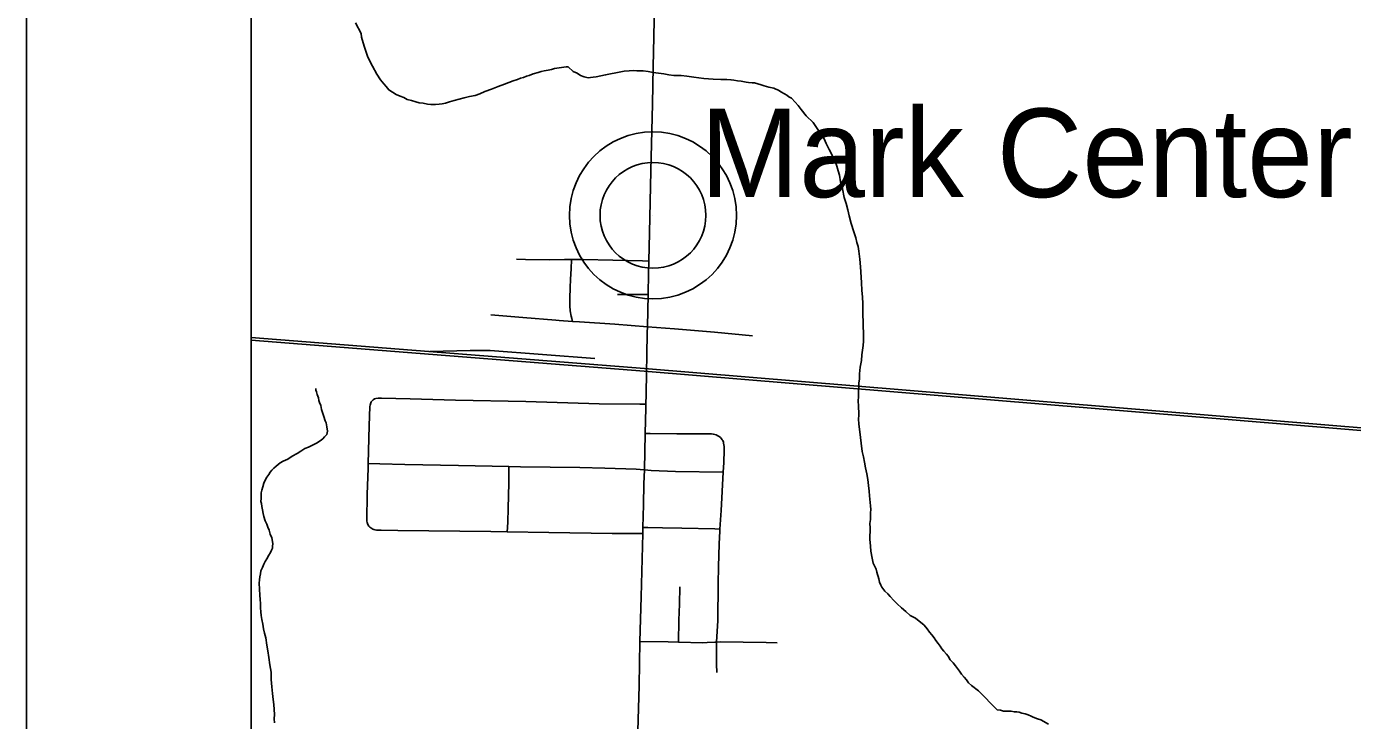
# Model space of a CAD drawing. Extents: x 2.1 to 73.9, y 4 to 26.
# Drawn here: x 41.859 to 42.449, y 23.011 to 23.321 of the extents above; entities that cross this region are included whole.
import ezdxf

# ---------------------------------------------------------------- set-up
doc = ezdxf.new("R2010")
doc.units = 0
for name, color, linetype in [('GM_X_County_Road', 7, 'Continuous'), ('GM_X_Minor_River', 7, 'Continuous'), ('GM_X_Rail_Line', 7, 'Continuous'), ('GM_X_Township_Road', 7, 'Continuous'), ('GM_X_Unincorporated', 7, 'Continuous'), ('GM_X_Unincorporated_Location', 7, 'Continuous'), ('GM_X_Unincorporated_Text', 7, 'Continuous'), ('SH_Data', 7, 'Continuous')]:
    doc.layers.add(name, color=color, linetype=linetype)

msp = doc.modelspace()

# ---------------------------------------------------------------- linework, layer by layer
at = {"layer": 'GM_X_County_Road'}
for p, q in [((42.13513, 23.18695), (42.13543, 23.20134)), ((42.13374, 23.12316), (42.13415, 23.13937)), ((42.13304, 23.09483), (42.1331, 23.09749))]:
    msp.add_line(p, q, dxfattribs=at)
for points in [[(42.13575, 23.21622), (42.13604, 23.22885), (42.13666, 23.25651), (42.13737, 23.28633), (42.13771, 23.30281), (42.13801, 23.31617), (42.13855, 23.34694), (42.13912, 23.37024), (42.13951, 23.39013), (42.1399, 23.40477)], [(42.13543, 23.20134), (42.13562, 23.21083), (42.13575, 23.21622)], [(42.13442, 23.15243), (42.13453, 23.15678), (42.13476, 23.16671), (42.13486, 23.17417), (42.13506, 23.18442), (42.13513, 23.18695)], [(42.13415, 23.13937), (42.13438, 23.15088), (42.13442, 23.15243)], [(42.1331, 23.09749), (42.13335, 23.10768), (42.13358, 23.11701), (42.13374, 23.12316)], [(42.13174, 23.04667), (42.13227, 23.06667), (42.13263, 23.07785), (42.13304, 23.09483)], [(42.12836, 22.90514), (42.1294, 22.94511), (42.13032, 22.98427), (42.13067, 23.00167), (42.13136, 23.02715), (42.13174, 23.04667)]]:
    msp.add_lwpolyline(points, dxfattribs=at)
at = {"layer": 'GM_X_Minor_River'}
for points in [[(42.00504, 23.32246), (42.00755, 23.31763), (42.00769, 23.31611), (42.0089, 23.31208), (42.01064, 23.30709), (42.0126, 23.30304), (42.01459, 23.29956), (42.01622, 23.29704), (42.01769, 23.29528), (42.01879, 23.29411), (42.01988, 23.29255), (42.02156, 23.29155), (42.02324, 23.29055), (42.02493, 23.28974), (42.02662, 23.28911), (42.02811, 23.28831), (42.03, 23.28787), (42.03188, 23.28724), (42.03339, 23.28681), (42.03529, 23.28656), (42.03717, 23.28612), (42.03869, 23.28608), (42.04078, 23.28601), (42.04231, 23.28615), (42.04364, 23.2863), (42.04518, 23.28663), (42.0469, 23.28715), (42.04902, 23.28784), (42.05131, 23.28834), (42.05343, 23.28903), (42.05591, 23.28953), (42.0584, 23.29002), (42.06052, 23.29071), (42.06264, 23.29178), (42.06572, 23.29283), (42.06861, 23.29407), (42.07149, 23.29512), (42.07342, 23.29582), (42.07534, 23.29652), (42.07726, 23.29721), (42.07861, 23.29774), (42.07995, 23.29808), (42.0813, 23.29861), (42.08245, 23.29895), (42.08419, 23.29966), (42.08649, 23.30034), (42.08783, 23.30068), (42.08917, 23.30102), (42.09089, 23.30135), (42.09242, 23.30168), (42.09377, 23.30202), (42.09892, 23.3028), (42.09988, 23.30277), (42.1021, 23.30081), (42.10378, 23.29999), (42.10527, 23.299), (42.10696, 23.29837), (42.10866, 23.29794), (42.10981, 23.2981), (42.11095, 23.29825), (42.11229, 23.2984), (42.1165, 23.29921), (42.1186, 23.29972)], [(42.1186, 23.29972), (42.12109, 23.30021), (42.12472, 23.30086), (42.12701, 23.30098), (42.12873, 23.30111), (42.13044, 23.30106), (42.13196, 23.30101), (42.13328, 23.30097), (42.13537, 23.30071), (42.13764, 23.30026), (42.1401, 23.3), (42.14237, 23.29973), (42.14464, 23.29928), (42.14691, 23.29902), (42.15014, 23.29892), (42.15261, 23.29865), (42.15582, 23.29817), (42.16018, 23.29766), (42.16436, 23.29734), (42.16777, 23.29723), (42.17043, 23.29715), (42.17233, 23.29709), (42.17366, 23.29686), (42.17517, 23.29662), (42.17688, 23.29637), (42.17914, 23.29592), (42.18009, 23.29589), (42.1818, 23.29565), (42.18275, 23.29562), (42.18425, 23.29519), (42.18576, 23.29477), (42.18708, 23.29435), (42.18915, 23.29371), (42.19142, 23.29326), (42.19236, 23.29285), (42.19348, 23.29244), (42.1946, 23.29164), (42.1961, 23.29083), (42.19722, 23.29023), (42.19814, 23.28944), (42.19927, 23.28884), (42.20092, 23.28707), (42.2022, 23.28552), (42.20367, 23.28376), (42.20587, 23.28103), (42.20901, 23.27808), (42.21391, 23.27071), (42.21479, 23.2686), (42.21604, 23.2659), (42.21765, 23.26281), (42.21873, 23.26069), (42.21942, 23.25858), (42.22012, 23.25646), (42.22063, 23.25455), (42.2211, 23.2515), (42.22196, 23.24843), (42.22279, 23.24461), (42.22365, 23.24192), (42.22432, 23.23905), (42.225, 23.23637), (42.22584, 23.23292), (42.22706, 23.22928), (42.22793, 23.22659), (42.22843, 23.22449), (42.22895, 23.22276), (42.22926, 23.22066), (42.22972, 23.21704), (42.22999, 23.21361), (42.23054, 23.20676), (42.23061, 23.20314), (42.2309, 23.20029), (42.231, 23.19724), (42.23109, 23.19401), (42.23126, 23.18736), (42.23134, 23.18394), (42.23142, 23.18052), (42.23117, 23.17862), (42.23092, 23.17654), (42.23066, 23.17446), (42.2304, 23.172), (42.22992, 23.16898), (42.22964, 23.16595), (42.22957, 23.16367), (42.22932, 23.16197), (42.22927, 23.16026), (42.22919, 23.15779), (42.22914, 23.15609), (42.22906, 23.15362), (42.2292, 23.15191), (42.22915, 23.15058), (42.2293, 23.14924), (42.22925, 23.14753), (42.2292, 23.14583), (42.22932, 23.14373), (42.23008, 23.13763), (42.23038, 23.13515), (42.23083, 23.13134), (42.23133, 23.12905), (42.23182, 23.12656), (42.23232, 23.12408), (42.2328, 23.1214)], [(41.98737, 23.15948), (41.98735, 23.15872), (41.98771, 23.15795), (41.98805, 23.1568), (41.98857, 23.15526), (41.98873, 23.15412), (41.98908, 23.15316), (41.9896, 23.15181), (41.98993, 23.15009), (41.99045, 23.14837), (41.99098, 23.14702), (41.99149, 23.1451), (41.99203, 23.14414), (41.99235, 23.14242), (41.99267, 23.14051), (41.99225, 23.139), (41.99126, 23.13789), (41.99047, 23.13697), (41.9893, 23.13606), (41.98775, 23.13515), (41.98408, 23.13337), (41.98254, 23.13266), (41.98079, 23.13157), (41.97905, 23.13049), (41.97692, 23.12923), (41.97498, 23.12796), (41.97286, 23.12707), (41.9715, 23.12636), (41.96975, 23.12489), (41.96877, 23.12397), (41.96779, 23.12305), (41.967, 23.12213), (41.9664, 23.1212), (41.9656, 23.11989), (41.9648, 23.11859), (41.96418, 23.11728), (41.96375, 23.11558), (41.96332, 23.11408), (41.9631, 23.11294), (41.96306, 23.1118), (41.96302, 23.11048), (41.96298, 23.10915), (41.96314, 23.10819), (41.96329, 23.10686), (41.96362, 23.10533), (41.96395, 23.1038), (41.96429, 23.10246), (41.9648, 23.10054), (41.96551, 23.099), (41.96604, 23.09766), (41.96657, 23.09631), (41.96708, 23.09458), (41.96779, 23.09285), (41.96812, 23.09132), (41.96828, 23.09018), (41.96806, 23.08923), (41.96803, 23.08829), (41.96762, 23.08735), (41.96721, 23.08641), (41.96641, 23.08511), (41.9656, 23.08361), (41.9648, 23.08231), (41.96419, 23.08119), (41.96358, 23.07969), (41.96296, 23.07819), (41.96273, 23.07687), (41.96249, 23.07554), (41.96226, 23.07422), (41.96222, 23.0727), (41.96243, 23.06738), (41.96256, 23.06547), (41.96269, 23.06357), (41.96282, 23.06167), (41.96296, 23.05995), (41.96309, 23.05824), (41.96342, 23.05652), (41.96373, 23.05442), (41.96405, 23.05232), (41.96456, 23.05041), (41.96506, 23.0483), (41.96553, 23.04506), (41.96603, 23.04257), (41.9665, 23.03952), (41.96697, 23.03628), (41.96744, 23.03303), (41.96753, 23.0298), (41.96781, 23.02656), (41.96809, 23.02351), (41.96839, 23.02085), (41.9687, 23.01856), (41.96882, 23.01646), (41.96894, 23.01418), (41.96888, 23.01228), (41.96901, 23.01038)], [(42.2328, 23.1214), (42.2333, 23.11892), (42.23359, 23.11625), (42.23389, 23.11377), (42.23402, 23.11168), (42.23416, 23.11015), (42.2343, 23.10863), (42.23445, 23.10711), (42.23459, 23.10558), (42.23454, 23.10406), (42.23449, 23.10255), (42.23445, 23.10103), (42.2342, 23.09933), (42.23433, 23.09742), (42.23428, 23.09571), (42.23422, 23.09382), (42.23417, 23.09211), (42.23432, 23.09078), (42.23446, 23.08925), (42.23458, 23.08697), (42.23524, 23.08391), (42.23574, 23.08161), (42.23645, 23.08007), (42.23699, 23.07891), (42.23732, 23.07757), (42.23767, 23.07661), (42.23783, 23.07566), (42.23818, 23.0747), (42.23852, 23.07317), (42.23905, 23.07182), (42.23959, 23.07086), (42.24086, 23.06911), (42.24216, 23.06793), (42.24326, 23.06675), (42.24492, 23.06499), (42.24639, 23.06342), (42.24823, 23.06166), (42.25028, 23.06007), (42.25212, 23.05831), (42.25456, 23.05709), (42.25845, 23.05393), (42.25973, 23.05237), (42.26082, 23.05082), (42.26174, 23.04965), (42.26284, 23.04828), (42.26356, 23.04712), (42.26466, 23.04576), (42.26557, 23.04459), (42.2663, 23.04343), (42.26722, 23.04245), (42.26832, 23.04108), (42.26905, 23.04011), (42.26995, 23.03856), (42.27124, 23.03719), (42.27233, 23.03583), (42.27325, 23.03466), (42.27416, 23.03349), (42.27507, 23.03214), (42.27617, 23.03077), (42.27727, 23.0296), (42.27818, 23.02824), (42.27948, 23.02706), (42.28254, 23.02469)], [(42.28254, 23.02469), (42.29085, 23.01631), (42.29237, 23.0161), (42.2937, 23.0157), (42.29484, 23.01568), (42.29598, 23.01566), (42.29712, 23.01564), (42.29845, 23.01543), (42.29959, 23.01541), (42.30073, 23.01521), (42.30186, 23.01481), (42.30338, 23.0144), (42.3047, 23.014), (42.30602, 23.01341), (42.30697, 23.01302), (42.30886, 23.01223), (42.31037, 23.01182), (42.31376, 23.00987)]]:
    msp.add_lwpolyline(points, dxfattribs=at)
at = {"layer": 'GM_X_Rail_Line'}
for points in [[(41.95853, 23.18223), (42.13383, 23.16839), (42.64315, 23.12618), (43.14232, 23.08596), (43.65014, 23.04512)], [(41.95853, 23.18098), (42.13373, 23.16715), (42.64305, 23.12494), (43.14222, 23.08472), (43.65005, 23.04388)], [(42.03826, 23.17593), (42.05614, 23.17643), (42.06508, 23.17633), (42.11163, 23.17283)]]:
    msp.add_lwpolyline(points, dxfattribs=at)
at = {"layer": 'GM_X_Township_Road'}
for points in [[(42.07681, 23.21707), (42.08085, 23.21688), (42.09142, 23.21685), (42.09821, 23.217), (42.10133, 23.21701)], [(42.10178, 23.18937), (42.10143, 23.19065), (42.10114, 23.19167), (42.10069, 23.19412), (42.10052, 23.19629), (42.10058, 23.19971), (42.10076, 23.20438), (42.10087, 23.20812), (42.10111, 23.21278), (42.10133, 23.21701)], [(42.10133, 23.21701), (42.10655, 23.21702), (42.13299, 23.2163), (42.13575, 23.21622)], [(42.12183, 23.20129), (42.12554, 23.20137), (42.13543, 23.20134)], [(42.06533, 23.19226), (42.07966, 23.19108), (42.09428, 23.18988)], [(42.09428, 23.18988), (42.0958, 23.18975), (42.10178, 23.18937)], [(42.10178, 23.18937), (42.10481, 23.18918), (42.12065, 23.18808), (42.13513, 23.18695)], [(42.13513, 23.18695), (42.1471, 23.186), (42.16501, 23.18461), (42.18197, 23.18299)], [(42.01078, 23.12608), (42.01116, 23.14277), (42.01152, 23.15139), (42.01164, 23.15207), (42.01186, 23.153), (42.01211, 23.15354), (42.01247, 23.15403), (42.01295, 23.15443)], [(42.01295, 23.15443), (42.01361, 23.15481), (42.0142, 23.15501), (42.01511, 23.15514), (42.01666, 23.1552), (42.02941, 23.15486), (42.04962, 23.15429), (42.08102, 23.15361), (42.11367, 23.15268), (42.13171, 23.15246), (42.13442, 23.15243)], [(42.13415, 23.13937), (42.13639, 23.13936), (42.14818, 23.13932), (42.16276, 23.13931), (42.1636, 23.13925), (42.16444, 23.13912), (42.16507, 23.13895), (42.1657, 23.13875), (42.16643, 23.13843), (42.16704, 23.13807), (42.16762, 23.13761)], [(42.1689, 23.1221), (42.16916, 23.12644), (42.16931, 23.13199), (42.16927, 23.13362), (42.1692, 23.13439), (42.16907, 23.13511), (42.16896, 23.13558), (42.1687, 23.13621), (42.16844, 23.13664), (42.16814, 23.13705), (42.16762, 23.13761)], [(42.01105, 23.09812), (42.0106, 23.09885), (42.01039, 23.09932), (42.01025, 23.09979), (42.01015, 23.10027), (42.01009, 23.10082), (42.01031, 23.11231), (42.01073, 23.1238), (42.01078, 23.12608)], [(42.01078, 23.12608), (42.01589, 23.12594), (42.02706, 23.12563), (42.05097, 23.12516), (42.07339, 23.12471)], [(42.07267, 23.0956), (42.07279, 23.09755), (42.07295, 23.10003), (42.07308, 23.10593), (42.07333, 23.11741), (42.07337, 23.12207), (42.07339, 23.12471)], [(42.07339, 23.12471), (42.07861, 23.12461), (42.10501, 23.12421), (42.11618, 23.12395), (42.13014, 23.12351), (42.13181, 23.12334), (42.13374, 23.12316)], [(42.13374, 23.12316), (42.13676, 23.1229), (42.14761, 23.12248), (42.1689, 23.1221)], [(42.16741, 23.09681), (42.16792, 23.10512), (42.1689, 23.1221)], [(42.01105, 23.09812), (42.01142, 23.0977), (42.01186, 23.0973), (42.01231, 23.09701), (42.01277, 23.09677), (42.01323, 23.0966), (42.0138, 23.09645), (42.01441, 23.09637), (42.01653, 23.0963), (42.02399, 23.09617), (42.06535, 23.09574), (42.07267, 23.0956)], [(42.07267, 23.0956), (42.09115, 23.09525), (42.11943, 23.09486), (42.13062, 23.09484), (42.13304, 23.09483)], [(42.1331, 23.09749), (42.13523, 23.09745), (42.14177, 23.09734), (42.15049, 23.0972), (42.16512, 23.09687), (42.16741, 23.09681)], [(42.16593, 23.04643), (42.16641, 23.05599), (42.16657, 23.07249), (42.16675, 23.07995), (42.16714, 23.09021), (42.16735, 23.09581), (42.16741, 23.09681)], [(42.14901, 23.04639), (42.14912, 23.05615), (42.14937, 23.06333), (42.14956, 23.07112)], [(42.13174, 23.04667), (42.14432, 23.04648), (42.14901, 23.04639)], [(42.14901, 23.04639), (42.15982, 23.04618), (42.16167, 23.04622), (42.16508, 23.04642), (42.16593, 23.04643)], [(42.16605, 23.03296), (42.16593, 23.03661), (42.16584, 23.04467), (42.16593, 23.04643)], [(42.16593, 23.04643), (42.16755, 23.04654), (42.18801, 23.04628), (42.19296, 23.04605)]]:
    msp.add_lwpolyline(points, dxfattribs=at)
at = {"layer": 'GM_X_Unincorporated'}
for radius in [0.0372, 0.02358]:
    msp.add_circle((42.13758, 23.23662), radius, dxfattribs=at)
at = {"layer": 'GM_X_Unincorporated_Location'}
msp.add_line((42.13758, 23.23662), (42.13758, 23.23662), dxfattribs=at)
at = {"layer": 'SH_Data'}
for p, q in [((41.85853, 25.00511), (41.85853, 18.00511)), ((41.95853, 24.90511), (41.95853, 18.10511))]:
    msp.add_line(p, q, dxfattribs=at)

# ---------------------------------------------------------------- texts
at = {"layer": 'GM_X_Unincorporated_Text'}
msp.add_text('Mark Center', height=0.0394886, rotation=0.00001, dxfattribs=at).set_placement((42.15871, 23.24474))

doc.saveas('drawing.dxf')
